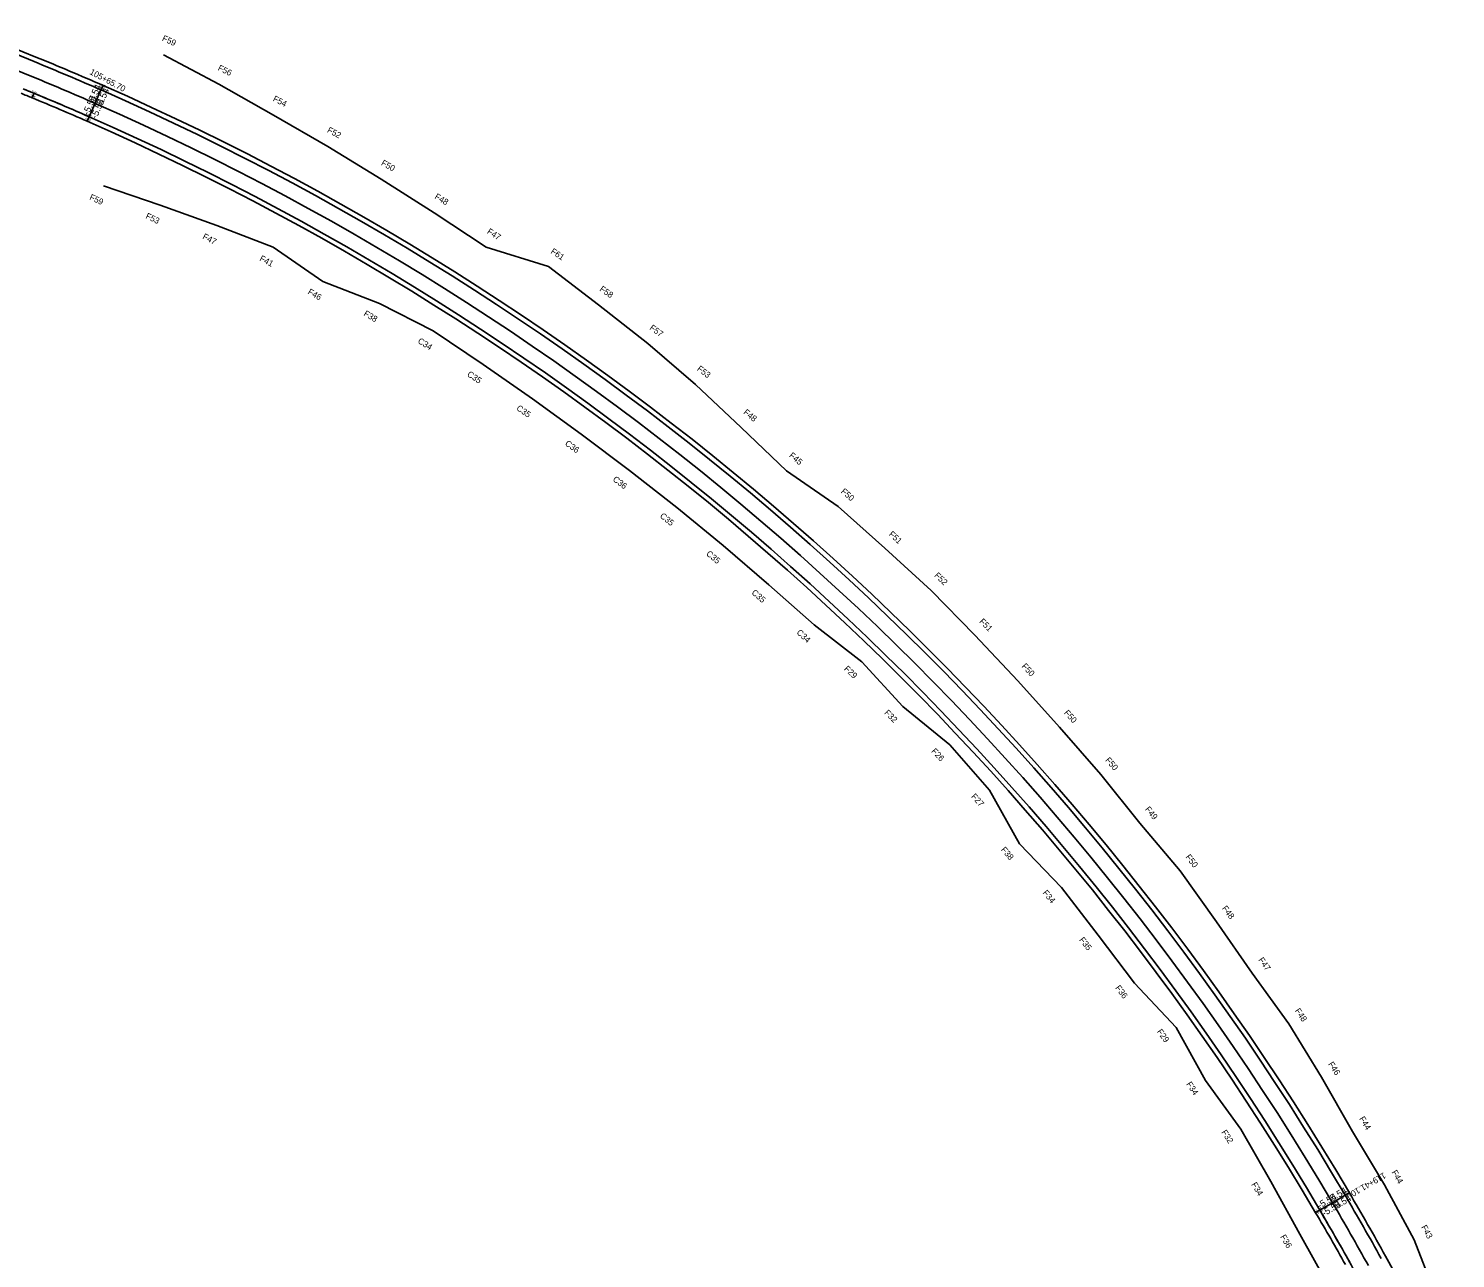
# Model space of a CAD drawing. Extents: x 2163527 to 2171930, y 206045 to 210376.
# Drawn here: x 2170508 to 2171675, y 206622 to 207627 of the extents above; entities that cross this region are included whole.
import ezdxf

# ---------------------------------------------------------------- set-up
doc = ezdxf.new("R2010")
doc.units = 0
for name, color, linetype in [('Default', 7, 'Continuous'), ('RD_PD_CstnLmt', 7, 'Continuous'), ('RD_PD_TX_CstnLmt', 7, 'Continuous'), ('RD_SHT_TX', 7, 'Continuous')]:
    doc.layers.add(name, color=color, linetype=linetype)

msp = doc.modelspace()

# ---------------------------------------------------------------- linework, layer by layer
at = {"layer": 'Default'}
for p, q in [((2170512.9, 207599.9), (2170403.4, 207644.6)), ((2170403.4, 207644.6), (2170512.9, 207599.9)), ((2170404.9, 207648.3), (2170514.4, 207603.6)), ((2170508.4, 207588.8), (2170398.8, 207633.4)), ((2170458.1, 207609.3), (2170508.4, 207588.8)), ((2170512.9, 207574), (2170511.4, 207570.3)), ((2170511.4, 207570.3), (2170512.9, 207574)), ((2170567.6, 207576.8), (2170562.8, 207565.8)), ((2170562.8, 207565.8), (2170567.6, 207576.8)), ((2170569.3, 207580.4), (2170567.6, 207576.8)), ((2170567.6, 207576.8), (2170569.3, 207580.4)), ((2170562.8, 207565.8), (2170558, 207554.8)), ((2170558, 207554.8), (2170562.8, 207565.8)), ((2170558, 207554.8), (2170556.4, 207551.1)), ((2170556.4, 207551.1), (2170558, 207554.8)), ((2171588.3, 206675.3), (2171584.8, 206673.3)), ((2171588.3, 206675.3), (2171584.8, 206673.3)), ((2171574.5, 206667.2), (2171564.2, 206661.1)), ((2171564.2, 206661.1), (2171574.5, 206667.2)), ((2171584.8, 206673.3), (2171574.5, 206667.2)), ((2171574.5, 206667.2), (2171584.8, 206673.3)), ((2171564.2, 206661.1), (2171560.7, 206659.1)), ((2171564.2, 206661.1), (2171560.7, 206659.1)), ((2171675, 206520.1), (2171617.8, 206623.6))]:
    msp.add_line(p, q, dxfattribs=at)
for radius, start, end in [(2212, 66.2989, 67.8388), (2212, 66.2989, 67.8388), (2216, 66.2989, 67.8388), (2200, 66.2989, 67.8388), (2200, 66.2989, 67.8388), (2184, 67.5832, 67.8388), (2188, 66.2989, 67.8388), (2188, 67.5832, 67.8388), (2188, 66.2989, 67.5832), (2212, 30.4786, 66.2989), (2212, 30.4786, 66.2989), (2216, 30.4786, 66.2989), (2184, 66.2989, 67.5832), (2200, 30.4786, 66.2989), (2200, 30.4786, 66.2989), (2184, 30.4786, 66.2989), (2188, 30.4786, 66.2989), (2188, 30.4786, 66.2989), (2216, 28.938, 30.4786), (2200, 28.938, 30.4786), (2200, 28.938, 30.4786), (2212, 28.938, 30.4786), (2212, 28.938, 30.4786), (2184, 29.1943, 30.4786), (2188, 28.938, 30.4786), (2188, 29.1943, 30.4786)]:
    msp.add_arc((2169678.5, 205551.3), radius, start, end, dxfattribs=at)
at = {"layer": 'RD_PD_CstnLmt'}
for p, q in [((2170618.7, 207605.5), (2170664, 207581.3)), ((2170664, 207581.3), (2170708.7, 207556.1)), ((2170708.7, 207556.1), (2170753.1, 207530.5)), ((2170753.1, 207530.5), (2170796.8, 207503.8)), ((2170796.8, 207503.8), (2170840, 207476.4)), ((2170569.7, 207498.3), (2170616.1, 207482.6)), ((2170616.1, 207482.6), (2170662.4, 207465.9)), ((2170840, 207476.4), (2170882.6, 207448.1)), ((2170662.4, 207465.9), (2170708.5, 207448.3)), ((2170708.5, 207448.3), (2170749, 207420.2)), ((2170882.6, 207448.1), (2170933.5, 207432.4)), ((2170933.5, 207432.4), (2170974.3, 207401.1)), ((2170749, 207420.2), (2170795.2, 207402.1)), ((2170795.2, 207402.1), (2170839.2, 207379.8)), ((2170974.3, 207401.1), (2171014.8, 207369.6)), ((2170839.2, 207379.8), (2170880, 207352.2)), ((2171014.8, 207369.6), (2171053.6, 207335.9)), ((2170880, 207352.2), (2170920.5, 207324.3)), ((2171053.6, 207335.9), (2171091, 207300.7)), ((2170920.5, 207324.3), (2170960.3, 207295.4)), ((2170960.3, 207295.4), (2170999.6, 207265.8)), ((2171091, 207300.7), (2171128.1, 207265.5)), ((2170999.6, 207265.8), (2171038.4, 207235.5)), ((2171128.1, 207265.5), (2171170.3, 207236.2)), ((2171038.4, 207235.5), (2171076.4, 207204.4)), ((2171170.3, 207236.2), (2171208.4, 207202.1)), ((2171076.4, 207204.4), (2171113.7, 207172.3)), ((2171208.4, 207202.1), (2171246.3, 207167.7)), ((2171113.7, 207172.3), (2171150.6, 207139.6)), ((2171246.3, 207167.7), (2171282, 207131)), ((2171150.6, 207139.6), (2171189.8, 207109.4)), ((2171282, 207131), (2171317.1, 207093.8)), ((2171189.8, 207109.4), (2171223.1, 207072.9)), ((2171317.1, 207093.8), (2171351.4, 207055.9)), ((2171223.1, 207072.9), (2171261.5, 207041.5)), ((2171351.4, 207055.9), (2171385, 207017.3)), ((2171261.5, 207041.5), (2171294.1, 207004.3)), ((2171385, 207017.3), (2171417.1, 206977.5)), ((2171294.1, 207004.3), (2171318.7, 206960.4)), ((2171417.1, 206977.5), (2171450, 206938.4)), ((2171318.7, 206960.4), (2171352.9, 206924.8)), ((2171450, 206938.4), (2171479.6, 206896.7)), ((2171352.9, 206924.8), (2171383, 206885.9)), ((2171479.6, 206896.7), (2171508.9, 206854.8)), ((2171383, 206885.9), (2171412.5, 206846.6)), ((2171508.9, 206854.8), (2171538.7, 206813.4)), ((2171412.5, 206846.6), (2171446.6, 206810.4)), ((2171446.6, 206810.4), (2171470.7, 206767.2)), ((2171538.7, 206813.4), (2171565.6, 206769.9)), ((2171565.6, 206769.9), (2171590.8, 206725.4)), ((2171470.7, 206767.2), (2171499.6, 206727.3)), ((2171499.6, 206727.3), (2171524.1, 206684.5)), ((2171590.8, 206725.4), (2171617, 206681.7)), ((2171524.1, 206684.5), (2171547.8, 206641.4)), ((2171617, 206681.7), (2171641.2, 206636.8)), ((2171547.8, 206641.4), (2171571.8, 206598.4)), ((2171641.2, 206636.8), (2171659.6, 206589.8))]:
    msp.add_line(p, q, dxfattribs=at)

# ---------------------------------------------------------------- texts
at = {"layer": 'Default'}
for s, height, rotation, p in [('-4.17', 1.84, 67.5832, (2170511.2, 207570.6)), ('-4.17', 1.84, 67.5832, (2170513.4, 207569.6)), ('5.54', 5.52, 66.2989, (2170562.2, 207566.6)), ('5.54', 5.52, 66.2989, (2170568.8, 207563.7)), ('5.54', 1.84, 66.2989, (2170567.5, 207577)), ('5.54', 1.84, 66.2989, (2170569.7, 207576.1)), ('-5.54', 5.52, 66.2989, (2170557.4, 207555.6)), ('-5.54', 5.52, 66.2989, (2170564, 207552.7)), ('-5.54', 1.84, 66.2989, (2170556.2, 207551.4)), ('-5.54', 1.84, 66.2989, (2170558.4, 207550.4)), ('-5.54', 5.52, 30.4786, (2171564.1, 206662.1)), ('5.54', 5.52, 30.4786, (2171574.5, 206668.2)), ('5.54', 1.84, 30.4786, (2171584.8, 206673.6)), ('5.54', 1.84, 30.4786, (2171586.1, 206671.6)), ('-5.54', 1.84, 30.4786, (2171560.7, 206659.4)), ('-5.54', 5.52, 30.4786, (2171567.8, 206655.9)), ('5.54', 5.52, 30.4786, (2171578.1, 206662)), ('-5.54', 1.84, 30.4786, (2171561.9, 206657.4))]:
    msp.add_text(s, height=height, rotation=rotation, dxfattribs=at).set_placement(p)
at = {"layer": 'RD_PD_TX_CstnLmt'}
for s, rotation, p in [('F59', 335.4056, (2170617.1, 207617.2)), ('F56', 334.1035, (2170662.7, 207593)), ('F54', 332.8013, (2170707.7, 207567.9)), ('F52', 331.4991, (2170752.1, 207542.4)), ('F50', 330.1969, (2170796.2, 207515.6)), ('F59', 335.4056, (2170557.7, 207487.3)), ('F48', 328.8947, (2170839.9, 207488.2)), ('F53', 334.1035, (2170603.6, 207472)), ('F47', 332.8013, (2170650.2, 207455.3)), ('F47', 327.5926, (2170882.8, 207459.8)), ('F61', 326.2904, (2170934.8, 207443.6)), ('F41', 331.4991, (2170696.8, 207437.5)), ('F46', 330.1969, (2170736.2, 207410.3)), ('F58', 324.9882, (2170974.8, 207412.9)), ('F38', 328.8947, (2170781.9, 207392.6)), ('F57', 323.686, (2171015.7, 207381.3)), ('C34', 327.5926, (2170826.1, 207370.3)), ('F53', 322.3839, (2171054.5, 207347.9)), ('C35', 326.2904, (2170866.5, 207343.2)), ('C35', 324.9882, (2170906.8, 207315.6)), ('F48', 321.0817, (2171092.4, 207312.4)), ('C36', 323.686, (2170946.5, 207286.8)), ('F45', 319.7795, (2171129.8, 207277.2)), ('C36', 322.3839, (2170985.6, 207257.6)), ('F50', 318.4773, (2171172.2, 207247.9)), ('C35', 321.0817, (2171024.1, 207227.7)), ('F51', 317.1752, (2171211.3, 207213)), ('C35', 319.7795, (2171062, 207196.9)), ('F52', 315.873, (2171248.6, 207179.4)), ('C35', 318.4773, (2171099.1, 207165.2)), ('F51', 314.5708, (2171285.4, 207141.8)), ('C34', 317.1752, (2171135.9, 207132.7)), ('F29', 315.873, (2171174.8, 207103.1)), ('F50', 313.2686, (2171320, 207105.3)), ('F32', 314.5708, (2171207.7, 207067.2)), ('F50', 311.9664, (2171354.6, 207067.3)), ('F26', 313.2686, (2171246.2, 207035.9)), ('F50', 310.6643, (2171388.4, 207028.7)), ('F27', 311.9664, (2171278.7, 206998.9)), ('F49', 309.3621, (2171420.9, 206988.6)), ('F38', 310.6643, (2171303.1, 206955.5)), ('F50', 308.0599, (2171454, 206949.6)), ('F34', 309.3621, (2171337.2, 206920.3)), ('F48', 306.7577, (2171483.9, 206907.7)), ('F35', 308.0599, (2171367.1, 206881.9)), ('F47', 305.4556, (2171513.6, 206865.6)), ('F36', 306.7577, (2171396.6, 206842.7)), ('F48', 304.1534, (2171543.5, 206824.1)), ('F29', 305.4556, (2171430.7, 206807)), ('F46', 302.8512, (2171570.7, 206780.5)), ('F34', 304.1534, (2171454.7, 206764.1)), ('F44', 301.549, (2171596.1, 206735.9)), ('F32', 302.8512, (2171483.4, 206724.8)), ('F44', 300.2469, (2171622.6, 206692.1)), ('F34', 301.549, (2171507.9, 206682.1)), ('F36', 300.2469, (2171531.6, 206639.4)), ('F43', 298.9447, (2171646.8, 206647.3))]:
    msp.add_text(s, height=5, rotation=rotation, dxfattribs=at).set_placement(p)
at = {"layer": 'RD_SHT_TX'}
for s, rotation, p in [('105+65.70', 331.9418, (2170557.9, 207589.9)), ('119+41.10', 210.2232, (2171616.3, 206692.2))]:
    msp.add_text(s, height=5, rotation=rotation, dxfattribs=at).set_placement(p)

doc.saveas('drawing.dxf')
